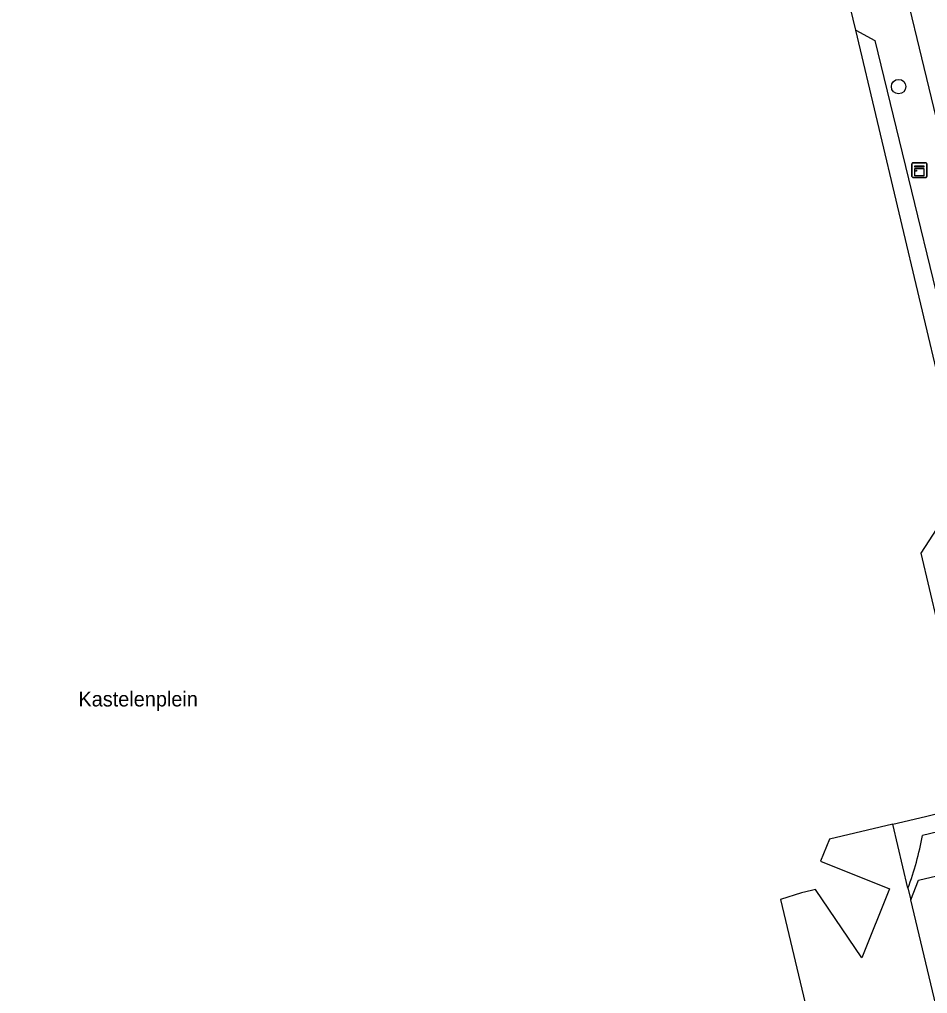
# Model space of a CAD drawing. Extents: x 158038 to 159242, y 380133 to 381214.
# Drawn here: x 158687.3 to 158748.4, y 381069.6 to 381135.2 of the extents above; entities that cross this region are included whole.
import ezdxf

# ---------------------------------------------------------------- set-up
doc = ezdxf.new("R2010")
doc.units = 0
for name, color, linetype in [('IMGEO_Boom', 7, 'Continuous'), ('IMGEO_Groenvoorziening', 7, 'Continuous'), ('IMGEO_Kast', 7, 'Continuous'), ('IMGEO_Openbare_ruimte_label', 7, 'Continuous'), ('IMGEO_Pand', 7, 'Continuous'), ('IMGEO_Voetpad_open', 7, 'Continuous')]:
    doc.layers.add(name, color=color, linetype=linetype)

msp = doc.modelspace()

# ---------------------------------------------------------------- linework, layer by layer
at = {"layer": 'IMGEO_Boom'}
msp.add_circle((158746.427, 381130.639), 0.489, dxfattribs=at)
at = {"layer": 'IMGEO_Groenvoorziening'}
msp.add_lwpolyline([(158745.488, 381052.299), (158750.386, 381060.047), (158750.616, 381060.466), (158750.732, 381061.354), (158747.242, 381075.952)], dxfattribs=at)
at = {"layer": 'IMGEO_Kast'}
for p, q in [((158747.323, 381124.594), (158747.323, 381125.435)), ((158747.323, 381125.435), (158747.323, 381124.594)), ((158747.398, 381125.519), (158748.239, 381125.519)), ((158748.239, 381125.519), (158747.398, 381125.519)), ((158748.323, 381125.444), (158748.323, 381124.603)), ((158748.323, 381124.603), (158748.323, 381125.444)), ((158748.248, 381124.519), (158747.407, 381124.519)), ((158747.407, 381124.519), (158748.248, 381124.519))]:
    msp.add_line(p, q, dxfattribs=at)
for points in [[(158747.518, 381125.309), (158748.118, 381125.309), (158748.118, 381125.224), (158747.518, 381125.224), (158747.518, 381125.309)], [(158747.518, 381125.134), (158748.118, 381125.134), (158748.118, 381124.645), (158747.518, 381124.645), (158747.518, 381125.134)]]:
    msp.add_lwpolyline(points, dxfattribs=at)
msp.add_circle((158747.602, 381124.983), 0.0377, dxfattribs=at)
for centre, start, end in [((158747.401, 381125.441), 92.4484, 184.28452), ((158747.401, 381125.441), 92.4484, 184.28452), ((158748.245, 381125.441), 2.4484, 94.28452), ((158748.245, 381125.441), 2.4484, 94.28452), ((158747.401, 381124.597), 182.4484, 274.28452), ((158747.401, 381124.597), 182.4484, 274.28452), ((158748.245, 381124.597), 272.4484, 4.28452), ((158748.245, 381124.597), 272.4484, 4.28452)]:
    msp.add_arc(centre, 0.0779, start, end, dxfattribs=at)
at = {"layer": 'IMGEO_Pand'}
for points in [[(158743.55, 381134.428), (158743.202, 381135.921), (158739.534, 381151.662), (158709.69, 381144.574), (158709.861, 381143.861), (158709.57, 381143.791), (158696.639, 381140.699)], [(158746.028, 381081.031), (158748.243, 381081.553), (158751.886, 381082.468), (158753.208, 381084.483), (158753.306, 381086.841), (158752.786, 381088.981), (158751.621, 381091.027), (158749.63, 381092.137), (158747.942, 381099.262), (158750.828, 381103.72), (158743.55, 381134.428)], [(158746.028, 381081.031), (158741.782, 381080.031), (158741.176, 381078.543), (158745.82, 381076.698), (158743.948, 381072.048), (158740.84, 381076.648), (158740.571, 381076.581), (158739.895, 381076.414), (158738.477, 381075.97), (158742.252, 381060.134), (158731.066, 381057.468), (158731.197, 381056.921), (158709.576, 381051.768), (158708.742, 381055.269), (158685.621, 381049.758), (158686.878, 381044.482), (158677.63, 381042.277), (158671.249, 381069.048), (158670.241, 381073.279), (158665.679, 381072.191), (158666.699, 381067.911), (158667.468, 381064.681), (158667.037, 381064.578)]]:
    msp.add_lwpolyline(points, dxfattribs=at)
at = {"layer": 'IMGEO_Voetpad_open'}
for points in [[(158748.243, 381143.26), (158745.545, 381142.608), (158749.419, 381126.543), (158753.981, 381107.372)], [(158743.55, 381134.428), (158744.82, 381133.731), (158751.389, 381106.745)], [(158751.389, 381106.745), (158752.171, 381103.533), (158749.286, 381099.049), (158750.731, 381092.955), (158752.523, 381091.977), (158753.963, 381089.417), (158754.545, 381086.936), (158754.44, 381084.069), (158752.634, 381081.384), (158748.03, 381080.286)], [(158747.056, 381076.728), (158746.028, 381081.031)], [(158747.242, 381075.952), (158747.769, 381077.264), (158750.895, 381078.011), (158754.834, 381060.053), (158748.721, 381049.977)], [(158747.056, 381076.728), (158747.242, 381075.952)]]:
    msp.add_lwpolyline(points, dxfattribs=at)
msp.add_arc((158727.576, 381083.973), 20.784, 339.59895, 349.78183, dxfattribs=at)

# ---------------------------------------------------------------- texts
at = {"layer": 'IMGEO_Openbare_ruimte_label'}
msp.add_text('Kastelenplein', height=1, dxfattribs=at).set_placement((158691.285, 381088.953))

doc.saveas('drawing.dxf')
